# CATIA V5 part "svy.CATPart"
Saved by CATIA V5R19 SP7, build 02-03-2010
Part number: Part1
Bounding box of the stored display mesh (mm): x -111 to 40, y 0 to 178.078, z -40.583 to -14.688
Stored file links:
  C:\DURATEC\Software\CATIA\CATIA forum\svy.CATPart
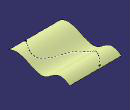
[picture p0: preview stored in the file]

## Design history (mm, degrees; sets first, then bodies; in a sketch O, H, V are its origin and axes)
Set1
  St3DCurveFeature1 "CATSt3DCurveFeatureName": Order 6, CreationType 2, ClosureMode false, ConstructionPoints ({point type Coord, X -4.4053, Y 5.7815, Z 0}; {point type Coord, X 16.5648, Y 57.3068, Z 0}; {point type Coord, X -65.6865, Y 87.9254, Z 0}; {point type Coord, X -51.5252, Y 173.6292, Z 0}), SymmetryMode false
  Sketch1 on yz-plane, origin (0, 0, 0), H (0, 1, 0), V (0, 0, 1)
    spline S1 through (0, -24.9371) (38.3557, -20.367) (117.1243, -33.1397) (130.489, -23.0622) (178.0784, -25.7573)
    point P1 (0, -24.9371)
    coincidence: P1 V
  Extrude1: Lim1 40, Lim2 111, Element1 Sketch1
  Project1: ToProject St3DCurveFeature1, Support Extrude1, Direction (0, 0, 1)
  Sweep1: type Segment, GuideCrv Project1, Length1 1.5, Length2 0, Angle 0, AngleEnd 180, DraftDirection (1, 0, 0)
  Sweep2: type Circle, Guide edge of Sweep1, Radius 0.5
  Split1: ToCut Sweep2, Cutting Extrude1
Body1 (main body)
